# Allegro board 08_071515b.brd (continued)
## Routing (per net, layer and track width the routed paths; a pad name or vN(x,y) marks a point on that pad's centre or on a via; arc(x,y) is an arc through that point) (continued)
ID0: length 18
  TOP w0.14: v2(52.2,10.54) 53.09,10.54 R136.2 53.22,9.6 52.83,9.2 U26.1
  L8_SIG w0.127: v2(52.2,10.54) 50.29,8.64 40.23,8.64 v1(39.42,7.83)
  BOTTOM w0.14: J2.76 v1(39.42,7.83)
ID1: length 17
  TOP w0.14: R137.2 v2(52.45,5.84) 52.45,7.19 U26.3
  L8_SIG w0.127: v2(52.45,5.84) 49.99,8.31 40.53,8.31 v1(40.05,7.83)
  BOTTOM w0.14: J2.78 v1(40.05,7.83)
INTVCC: length 16.7
  TOP w0.254: v2(24.83,13.08) 23.24,13.08 22.55,13.77 R100.2 20.43,14.62 20.42,14.62 20.23,14.81 20.23,14.81 20.05,14.99 VR1.3
  TOP w0.305: R94.2 v2(15.34,12.17)
  L8_SIG w0.305: v2(24.83,13.08) 21.4,13.08 21.14,12.83 16,12.83 v2(15.34,12.17)
JTG0_TCK/SWCLK: length 70.6
  TOP w0.14: v1(5.46,28.83) 4.27,28.83 2.71,30.39 2.71,46.84 1.94,47.6 1.94,55.25 3.04,56.34 5.51,56.34 6.03,55.82 6.03,54.67 5.08,53.72
  TOP w0.203: U1.B11 v1(33.82,59.74)
  L5_SIG w0.127: v1(33.82,59.74) 33.07,58.99 33.07,57.25 32.75,56.93 20.1,56.93 16.13,52.96 6.68,52.96 5.92,53.72 5.08,53.72
  BOTTOM w0.14: v1(5.46,28.83) 5.59,28.7 J3.50
JTG0_TD0/SW0: length 77.7
  TOP w0.14: v1(8.26,27.81) 4.65,27.81 2.35,30.12 2.35,46.64 1.46,47.52 1.46,56.2 2.16,56.9 5.71,56.9 6.48,56.13 6.48,53.85 P6.6
  TOP w0.203: U1.C11 v1(33.82,58.94)
  L5_SIG w0.127: v1(33.82,58.94) 33.38,58.5 33.38,56.87 32.64,56.13 19.94,56.13 16.26,52.45 P6.6
  BOTTOM w0.14: J3.52 8,28.07 v1(8.26,27.81)
JTG0_TDI: length 85.4
  TOP w0.14: 5.08,51.18 6.92,53.02 6.92,56.39 5.84,57.47 1.46,57.47 0.86,56.86 0.86,47.47 2.01,46.32 2.01,29.84 4.8,27.05 v1(8.26,27.05)
  TOP w0.203: U1.C13 v1(35.42,59.74)
  L5_SIG w0.127: 5.08,51.18 5.84,51.18 6.73,52.07 16.38,52.07 20.07,55.75 23.75,55.75 24.15,55.35 32.87,55.35 34.21,56.68 34.21,59.07 34.46,59.33 35.01,59.33 v1(35.42,59.74)
  BOTTOM w0.14: J3.54 7.87,27.43 v1(8.26,27.05)
JTG0_TMS/SWDIO: length 72
  TOP w0.14: v1(8.26,29.08) 7.91,29.43 4.29,29.43 3.1,30.62 3.1,47 2.28,47.82 2.28,55.11 3.17,56.01 4.83,56.01 5.08,55.75 P6.2
  TOP w0.203: U1.C12 v1(34.62,59.74)
  L5_SIG w0.127: P6.2 5.92,54.99 7.57,53.34 16,53.34 17.14,54.48 17.14,56.01 18.41,57.28 24,57.28 24.45,57.73 32.63,57.73 32.79,57.89 32.79,59.59 33.4,60.2 34.16,60.2 v1(34.62,59.74)
  BOTTOM w0.14: v1(8.26,29.08) 8,29.34 J3.48
JTG0_TRST*: length 75.3
  TOP w0.14: P6.9 6.1,47.62 R78.2 R79.1 v1(9.02,45.54) ; v1(19.68,64.14) 29.42,64.14 U1.A10
  L4_SIG w0.127: v1(5.46,26.54) 6.48,27.56 6.48,42.99 v1(9.02,45.54)
  L5_SIG w0.127: P6.9 2.92,49.91 2.41,50.42 2.41,55.37 3.56,56.52 11.18,56.52 12.07,55.63 12.83,55.63 13.44,56.24 15.6,56.24 18.67,59.31 19.43,59.31 19.68,59.56 v1(19.68,64.14)
  BOTTOM w0.14: v1(5.46,26.54) 5.72,26.8 J3.56
LTC3310_EN: length 2.3
  TOP w0.254: U16.1 33.66,15.64 33.66,14.99 33.91,14.73 v2(33.91,14.54)
  BOTTOM w0.254: v2(33.91,14.54) 33.91,13.6 R92.2
PA_00/SPI2_MISO/XSPI0_MISO/PWM0_AH/SMC0_D00: length 38.7
  TOP w0.14: U23.6 21.99,30.88 21.46,30.35 v1(21.46,30.1) ; v1(22.35,35.43) 22.35,36.16 U22.6
  TOP w0.203: U1.N3 v1(26.62,50.94)
  L7_SIG w0.127: v1(22.35,35.43) 21.97,35.81 19.81,35.81 18.57,37.06 18.57,44.6 19.68,45.72 20.7,45.72 22.1,47.12 22.1,51.56 22.69,52.15 26.78,52.15 27.03,51.9 27.03,51.35 v1(26.62,50.94)
  L8_SIG w0.127: v1(22.35,35.43) 22.35,33.93 21.64,33.22 20.14,33.22 19.91,32.99 19.91,30.45 20.27,30.1 v1(21.46,30.1)
PA_00/SPI2_MISO/XSPI0_MISO/PWM0_AH/SMC0_D00_Z: length 33.6
  TOP w0.14: v1(21.46,30.99) 21.85,31.38 U23.5
  L5_SIG w0.127: v1(21.46,30.99) 22.07,30.38 22.07,9.07 22.76,8.38 22.76,7.7 22.19,7.14 19.47,7.14 v1(16.56,4.23)
  BOTTOM w0.14: J2.3 v1(16.56,4.23)
PA_01/SPI2_MOSI/XSPI0_MOSI/PWM0_AL/SMC0_D01: length 30.3
  TOP w0.14: v1(21.46,32.77) 21.85,32.38 U23.3 ; U22.3 21.85,37.71 v1(21.46,38.1)
  TOP w0.203: U1.P3 v1(26.62,50.14)
  L4_SIG w0.127: v1(21.46,38.1) 21.92,37.64 21.92,33.22 v1(21.46,32.77)
  L7_SIG w0.127: v1(26.62,50.14) 26.57,50.14 26.23,50.47 26.23,51.24 26.14,51.33 22.62,51.33 22.48,51.18 22.48,46.86 18.9,43.28 18.9,38.51 19.3,38.1 v1(21.46,38.1)
PA_01/SPI2_MOSI/XSPI0_MOSI/PWM0_AL/SMC0_D01_Z: length 38.9
  TOP w0.14: U23.2 21.99,32.88 21.46,33.4 v1(21.46,33.66)
  L5_SIG w0.127: v1(17.19,1.94) 17.19,4.31 19.68,6.81 22.45,6.81 23.09,7.44 23.09,8.52 22.48,9.13 22.48,32.64 v1(21.46,33.66)
  BOTTOM w0.14: J2.5 v1(17.19,1.94)
PA_02/SPI2_D2/XSPI0_D2/TWI3_SCL/SMC0_D02/TM0_ACLK3: length 27.3
  TOP w0.14: U22.8 v1(25.32,35.51) ; U23.8 v1(25.32,30.18)
  TOP w0.203: U1.P2 v1(25.82,50.14)
  L7_SIG w0.127: v1(25.82,50.14) 25.41,50.55 24.13,50.55 23.47,49.89 23.47,45.45 21.77,43.75 21.77,39.87 23.23,38.4 24.76,38.4 25.32,37.84 v1(25.32,35.51) v1(25.32,30.18)
PA_02/SPI2_D2/XSPI0_D2/TWI3_SCL/SMC0_D02/TM0_ACLK3_Z: length 35
  TOP w0.14: U23.9 26.02,30.88 26.54,30.35 v1(26.54,30.1)
  L5_SIG w0.127: v1(17.83,4.23) 20.03,6.43 22.91,6.43 23.97,7.49 23.97,11.73 23.09,12.62 23.09,16.69 24.84,18.44 25.69,18.44 26.29,19.04 26.29,27.69 26.06,27.91 26.06,29.62 v1(26.54,30.1)
  BOTTOM w0.14: J2.7 v1(17.83,4.23)
PA_03/SPI2_D3/XSPI0_D3/TWI3_SDA/SMC0_D03: length 26.8
  TOP w0.14: v1(26.54,38.1) 26.15,37.71 U22.12 ; v1(26.54,32.77) 26.15,32.38 U23.12
  TOP w0.203: U1.R3 v1(26.62,49.34)
  L4_SIG w0.127: v1(26.54,32.77) 26.09,33.22 26.09,37.64 v1(26.54,38.1)
  L7_SIG w0.127: v1(26.62,49.34) 26.21,49.75 24.23,49.75 23.75,49.28 23.75,45.34 22.1,43.69 22.1,40.01 23.37,38.73 24.89,38.73 25.65,37.97 25.93,37.97 26.06,38.1 v1(26.54,38.1)
PA_03/SPI2_D3/XSPI0_D3/TWI3_SDA/SMC0_D03_Z: length 38.3
  TOP w0.14: U23.11 v1(26.54,31.88)
  L5_SIG w0.127: v1(26.54,31.88) 27,31.42 27,27.76 26.67,27.43 26.67,18.95 25.83,18.11 24.97,18.11 23.42,16.55 23.42,12.76 24.38,11.79 24.38,7.12 23.31,6.05 21.05,6.05 18.46,3.46 v1(18.46,1.94)
  BOTTOM w0.14: J2.9 v1(18.46,1.94)
PA_04/SPI2_CLK/XSPI0_CLK/PWM0_BH/SMC0_D04: length 24
  TOP w0.14: v1(27.81,32.77) 28.2,32.38 U28.3 ; v1(27.81,38.1) 28.2,37.71 U27.3
  TOP w0.203: U1.R1 v1(25.02,49.34)
  L4_SIG w0.127: v1(27.81,38.1) 27.38,37.67 27.38,33.15 27.76,32.77 v1(27.81,32.77)
  L7_SIG w0.127: v1(25.02,49.34) 24.54,49.34 24.03,48.83 24.03,45.22 23.29,44.49 23.29,40.5 23.79,40.01 23.79,39.46 24.18,39.07 25.03,39.07 25.56,38.53 27.38,38.53 v1(27.81,38.1)
PA_04/SPI2_CLK/XSPI0_CLK/PWM0_BH/SMC0_D04_Z: length 41.2
  TOP w0.14: U28.2 28.34,32.88 27.81,33.4 v1(27.81,33.66)
  L5_SIG w0.127: v1(19.1,1.94) 19.1,3.63 20.58,5.11 23.4,5.11 23.55,5.26 23.55,5.66 25.24,7.35 25.24,11.4 23.75,12.89 23.75,16.42 25.11,17.78 25.96,17.78 27,18.82 27,27.2 27.38,27.58 27.38,33.22 v1(27.81,33.66)
  BOTTOM w0.14: J2.11 v1(19.1,1.94)
PA_05/SPI2_SEL1B/XSPI0_SEL1B/FPLL_DBG_LOCK/SMC0_D05/SPI2_SSB: length 28.3
  TOP w0.14: U27.6 28.34,36.21 27.81,35.69 v1(27.81,35.43) ; v1(27.81,30.1) 27.81,30.35 28.34,30.88 U28.6
  TOP w0.203: U1.T2 v1(25.82,48.54)
  L4_SIG w0.127: v1(27.81,35.43) 28.24,35 28.24,30.53 v1(27.81,30.1)
  L7_SIG w0.127: v1(25.82,48.54) 25.43,48.93 24.67,48.93 24.31,48.56 24.31,44.75 23.62,44.07 23.62,40.64 24.06,40.21 24.94,40.21 25.53,39.62 27.81,39.62 28.57,38.86 28.57,36.2 v1(27.81,35.43)
PA_05/SPI2_SEL1B/XSPI0_SEL1B/FPLL_DBG_LOCK/SMC0_D05/SPI2_SSB_Z: length 38.6
  TOP w0.14: U28.5 28.2,31.38 v1(27.81,30.99)
  L5_SIG w0.127: v1(27.81,30.99) 28.24,30.56 28.24,27.76 27.36,26.87 27.36,18.7 26.1,17.45 25.25,17.45 24.08,16.28 24.08,13.03 25.59,11.52 25.59,7.05 24.64,6.1 24.64,5.26 24.18,4.8 20.8,4.8 19.73,3.73 v1(19.73,1.94)
  BOTTOM w0.14: J2.13 v1(19.73,1.94)
PA_06/SPI0_CLK/UART0_TXB/XSPI0_D4/SMC0_D06/TM0_ACLK1: length 61.4
  TOP w0.14: U29.3 34.55,37.71 v1(34.16,38.1) ; U7.9 18.32,75.82 v2(20.19,75.82) ; v1(34.16,32.77) 34.55,32.38 U30.3
  TOP w0.203: U1.T3 v1(27.42,48.54)
  L4_SIG w0.127: v2(20.19,75.82) 20.19,75.82 19.43,75.06 19.43,74.42 19.94,73.91 21.21,73.91 21.97,73.15 21.97,49.02 22.35,48.64 24.26,48.64 24.54,48.93 27.03,48.93 v1(27.42,48.54) ; v1(34.16,38.1) 33.71,37.64 33.71,33.22 v1(34.16,32.77)
  L7_SIG w0.127: v1(34.16,38.1) 33.73,38.53 33.73,40.08 34.29,40.64 34.29,41.53 33.02,42.8 28.57,42.8 27.71,43.67 27.71,44.79 27.81,44.89 27.81,48.13 27.42,48.53 v1(27.42,48.54)
PA_06/SPI0_CLK/UART0_TXB/XSPI0_D4/SMC0_D06/TM0_ACLK1_Z: length 62.2
  TOP w0.14: v1(16.56,5.54) 17.27,4.83 17.27,3.68 18.29,2.67 28.53,2.67 v1(29.26,1.94) ; U30.2 34.69,32.88 34.16,33.4 v1(34.16,33.66)
  L5_SIG w0.127: v1(34.16,33.66) 33.66,33.15 33.66,31.75 33.35,31.45 31.95,31.45 29.44,28.93 29.44,27.76 28.55,26.87 28.55,8.67 28.07,8.19 28.07,6.73 28.57,6.22 28.57,5.4 28.26,5.08 27.33,5.08 26.8,4.55 26.8,3.05 27.9,1.94 v1(29.26,1.94)
  BOTTOM w0.14: J2.15 20.37,3.99 20.23,4.13 18.7,4.13 18.13,4.7 17.4,4.7 v1(16.56,5.54) J2.4 ; J2.43 v1(29.26,1.94)
PA_07/SPI0_MISO/UART0_RXB/XSPI0_D5/SMC0_D07/TM0_ACI0: length 72.7
  TOP w0.14: U29.6 34.69,36.21 34.16,35.69 v1(34.16,35.43) ; U30.6 34.69,30.88 34.16,30.35 v1(34.16,30.1) ; U7.12 v2(16.19,77.74)
  TOP w0.203: U1.V1 v1(25.02,46.94)
  L4_SIG w0.127: v1(34.16,35.43) 34.59,35 34.59,30.53 v1(34.16,30.1) ; v2(16.19,77.74) 17.26,77.74 17.53,77.47 17.53,75.44 16.76,74.68 16.76,73.53 17.14,73.15 17.14,70.99 18.41,69.72 18.41,67.95 18.8,67.56 18.8,65.53 18.67,65.41 17.78,65.41 17.57,65.19 17.57,60.28 17.91,59.94 17.91,57.28 16.81,56.18 16.81,51.89 18.8,49.91 18.8,47.5 19.35,46.94 v1(25.02,46.94)
  L7_SIG w0.127: v1(34.16,35.43) 33.71,35.89 32.26,35.89 32.13,36.02 32.13,40.01 32.65,40.53 32.65,41.12 32.11,41.66 26.16,41.66 25.21,42.61 25.21,43.69 25.41,43.88 25.41,46.6 25.07,46.94 v1(25.02,46.94)
PA_07/SPI0_MISO/UART0_RXB/XSPI0_D5/SMC0_D07/TM0_ACI0_Z: length 58.6
  TOP w0.14: v1(34.16,30.99) 34.55,31.38 U30.5 ; v1(21,1.94) 21.77,1.17 31.78,1.17 32.38,1.78 32.38,4.32 31.95,4.76 30.17,4.76 v1(29.72,4.3)
  L5_SIG w0.127: v1(29.72,4.3) 29.72,4.79 29.89,4.96 29.89,6.05 29.05,6.89 29.05,14.68 29.82,15.44 29.82,17.75 28.96,18.62 28.96,26.59 29.77,27.41 29.77,28.57 30.95,29.75 31.93,29.75 32.18,30 32.74,30.56 33.73,30.56 v1(34.16,30.99)
  BOTTOM w0.14: J2.6 17.19,5.61 17.72,5.08 18.16,5.08 18.8,4.45 20.72,4.45 21,4.16 J2.17 v1(21,1.94) ; v1(29.72,4.3) 29.72,4.19 29.89,4.02 J2.45
PA_08/SPI0_MOSI/UART0_RTSB/XSPI0_D6/SMC0_D08/TM0_ACLK2: length 73.5
  TOP w0.14: v2(11.05,78.74) 11.4,78.39 U7.2 ; U30.8 v1(38.1,30.18) ; U29.8 v1(38.1,35.51)
  TOP w0.203: U1.U3 v1(26.62,47.74)
  L4_SIG w0.127: v2(19.3,73.41) 20.95,73.41 21.43,72.93 21.43,48.67 21.97,48.13 26.16,48.13 26.55,47.74 v1(26.62,47.74) ; v1(38.1,30.18) v1(38.1,35.51)
  L5_SIG w0.127: v2(19.3,73.41) 19.3,74.17 18.29,75.18 16,75.18 12.45,78.74 v2(11.05,78.74)
  L7_SIG w0.127: v1(26.62,47.74) 26.62,47.67 27.01,47.29 27.01,44.85 26.92,44.77 26.92,42.93 27.43,42.42 32.51,42.42 33.39,41.54 33.39,37.99 33.71,37.67 34.72,37.67 35.43,36.96 35.43,36.32 36.24,35.51 v1(38.1,35.51)
PA_08/SPI0_MOSI/UART0_RTSB/XSPI0_D6/SMC0_D08/TM0_ACLK2_Z: length 54.4
  TOP w0.14: U30.9 38.72,30.88 39.24,30.35 v1(39.24,30.1) ; v1(30.53,4.23) 29.35,3.05 22.82,3.05 v1(21.64,4.23)
  L5_SIG w0.127: v1(30.53,4.23) 31.25,3.51 36.5,3.51 38.07,5.08 38.07,18.48 36.25,20.31 36.25,27.1 v1(39.24,30.1)
  BOTTOM w0.14: J2.8 17.83,5.61 17.98,5.46 18.27,5.46 18.97,4.76 21.1,4.76 v1(21.64,4.23) J2.19 ; J2.47 v1(30.53,4.23)
PA_09/SPI0_SEL1B/UART0_CTSB/XSPI0_D7/SMC0_D09/SPI0_SSB: length 76.7
  TOP w0.14: v1(39.24,32.77) 38.85,32.38 U30.12 ; v1(39.24,38.1) 38.85,37.71 U29.12 ; U7.5 v2(13.86,76.44)
  TOP w0.203: U1.V2 v1(25.82,46.94)
  L4_SIG w0.127: v2(18.16,64.77) 19.3,63.63 19.3,47.62 19.58,47.35 25.41,47.35 v1(25.82,46.94) ; v1(39.24,32.77) 38.81,33.2 38.81,37.67 v1(39.24,38.1)
  L5_SIG w0.127: v2(13.86,76.44) 15.49,74.8 18.03,74.8 18.41,74.42 18.41,73.66 17.53,72.77 17.53,71.63 18.69,70.46 18.69,65.3 v2(18.16,64.77)
  L7_SIG w0.127: v1(39.24,38.1) 38.73,37.59 38.73,35.18 38.61,35.05 36.2,35.05 34.49,36.75 32.71,36.75 32.46,37.01 32.46,39.83 33.02,40.39 33.02,41.22 32.2,42.04 26.92,42.04 26.42,42.55 26.42,43.69 26.21,43.9 26.21,46.44 25.82,46.82 v1(25.82,46.94)
PA_09/SPI0_SEL1B/UART0_CTSB/XSPI0_D7/SMC0_D09/SPI0_SSB_Z: length 57
  TOP w0.14: v1(22.27,1.94) 22.71,1.5 30.33,1.5 31.02,2.19 31.02,3.97 v1(31.37,4.32) ; U30.11 v1(39.24,31.88)
  L5_SIG w0.127: v1(39.24,31.88) 38.58,31.22 38.58,29.95 35.86,27.23 35.86,20.22 37.74,18.34 37.74,5.74 35.84,3.84 31.85,3.84 v1(31.37,4.32)
  BOTTOM w0.14: v1(22.27,1.94) J2.21 22.27,4.27 21.49,5.05 19.2,5.05 18.46,5.79 J2.10 ; J2.49 31.16,4.11 v1(31.37,4.32)
PA_10/TWI0_SCL/SPI1_CLK/TM0_TMR0/SMC0_D10: length 80.5
  TOP w0.14: R49.1 v2(20.57,32.64)
  TOP w0.203: U1.U2 v1(25.82,47.74)
  L4_SIG w0.127: v2(20.57,32.64) 19.43,31.5 19.43,29.51 18.21,28.3 15.88,28.3 15.27,27.69 15.27,24.33 16.7,22.9 16.7,11.62 15.19,10.11 15.19,8.66 16.02,7.83 v1(19.73,7.83)
  L7_SIG w0.127: v2(20.57,32.64) 18.24,34.98 18.24,45.54 19.81,47.12 21.08,47.12 21.72,47.75 21.72,52.96 22.08,53.33 27.32,53.33 27.83,52.81 27.83,49.75 v1(25.82,47.74)
  BOTTOM w0.14: J2.31 25.45,4.27 25.02,4.7 22.35,4.7 21.71,5.35 20,5.35 19.73,5.61 J2.14 v1(19.73,7.83)
PA_11/TWI0_SDA/SPI1_MISO/HADC_EOC_OUT/SMC0_D11/TM0_ACI4: length 89.6
  TOP w0.14: R52.2 v2(20.57,35.18)
  TOP w0.203: U1.V8 v1(30.62,46.94)
  L4_SIG w0.127: v1(20.37,7.83) 20.37,7.35 20.21,7.19 16.05,7.19 14.76,8.48 14.76,10.19 16.37,11.8 16.37,22.76 14.94,24.2 14.94,27.86 15.7,28.63 18.07,28.63 19.08,29.63 19.08,33.68 v2(20.57,35.18)
  L8_SIG w0.127: v2(20.57,35.18) 20.07,35.69 12.7,35.69 9.53,38.86 9.53,44.07 11.43,45.97 20.44,45.97 20.46,45.95 21.82,45.95 23.2,47.33 30.23,47.33 v1(30.62,46.94)
  BOTTOM w0.14: v1(20.37,7.83) J2.16 20.37,5.78 20.51,5.64 21.92,5.64 22.48,5.08 25.16,5.08 26.08,4.16 J2.33
PA_12/FLG0/SPI1_MOSI/TM0_TMR1/SMC0_D12: length 86.1
  TOP w0.14: U4.D3 14.22,35.42 14.22,37.21 15.62,38.61 v2(17.53,38.61)
  TOP w0.203: U1.W6 v1(29.02,46.14)
  L4_SIG w0.127: v1(21,7.83) 21.79,7.04 24.01,7.04 24.33,7.36 24.33,8.01 24.71,8.39 24.71,11.44 22.71,13.45 22.71,28.59 25.4,31.28 25.4,34.67 24.89,35.18 24.89,35.82 25.52,36.44 25.52,39.8 27.62,41.91 28.31,41.91 29.59,43.19 29.59,44.07 29.43,44.23 29.43,45.73 v1(29.02,46.14)
  L8_SIG w0.127: v2(17.53,38.61) 12.57,38.61 11.94,39.24 11.94,40.26 10.54,41.66 10.54,43.94 11.84,45.24 18.52,45.24 18.54,45.21 23.62,45.21 24.14,45.73 28.61,45.73 v1(29.02,46.14)
  BOTTOM w0.14: J2.18 v1(21,7.83)
PA_13/FLG1/SPI1_SEL1B/TM0_TMR2/SMC0_D13/SPI1_SSB: length 63.8
  TOP w0.14: U9.2 v2(16.32,41.27)
  TOP w0.203: U1.Y6 v1(29.02,45.34)
  L4_SIG w0.127: v1(21.64,7.83) 22.1,7.37 23.88,7.37 24,7.49 24,8.38 24.38,8.76 24.38,11.3 22.38,13.31 22.38,28.73 24.21,30.56 24.21,38.3 25.18,39.28 25.18,41.82 25.78,42.42 27.43,42.42 29.02,44.01 v1(29.02,45.34)
  L8_SIG w0.127: v1(29.02,45.34) 28.51,44.83 28.51,44.57 28.68,44.4 28.68,43.99 28.51,43.82 28.51,42.8 28,42.29 19.43,42.29 18.41,41.27 v2(16.32,41.27)
  BOTTOM w0.14: J2.20 v1(21.64,7.83)
PA_14/TWI2_SCL/SPI1_D2/UART1_RXB/SMC0_D14/TM0_ACI1: length 107.8
  TOP w0.14: v2(52.83,21.21) 52.83,23.11 52.71,23.24 U21.2 ; U10.2 v2(10.09,41.27)
  TOP w0.203: U1.W7 v1(29.82,46.14)
  L4_SIG w0.127: v1(25.45,5.54) 25.45,9.91 27.46,11.92 27.46,14.2 26.87,14.78 26.41,14.78 26.06,15.13 26.06,15.4 26.06,17.93 27.3,19.18 27.3,28.45 v1(26.54,29.21) 27,29.67 28.73,29.67 29.18,30.12 29.18,34.21 29.17,34.23 29.17,40.17 29.57,40.56 29.57,41.88 30.1,42.42 30.1,44.07 30.23,44.2 30.23,45.73 v1(29.82,46.14)
  L8_SIG w0.127: v1(29.82,46.14) 29.41,46.55 24.33,46.55 23.37,45.59 11.72,45.59 10.09,43.96 v2(10.09,41.27) ; v1(26.54,29.21) 27.18,28.57 28.19,28.57 28.5,28.88 41.99,28.88 46.23,24.64 46.23,20.96 46.57,20.61 52.23,20.61 v2(52.83,21.21)
  BOTTOM w0.14: J2.32 v1(25.45,5.54)
PA_15/TWI2_SDA/SPI1_D3/UART1_TXB/SMC0_D15/FPLL_REF_CLK: length 97.6
  TOP w0.14: v2(12.26,41.27) U5.2 ; U20.2 48.2,23.24 48.39,23.05 v2(48.39,21.21)
  TOP w0.203: U1.W8 v1(30.62,46.14)
  L4_SIG w0.127: v1(26.08,7.83) 26.08,9.95 27.79,11.66 27.79,14.38 27.05,15.11 26.54,15.11 26.39,15.27 26.39,17.63 27.81,19.05 v1(27.81,29.21) 29.18,29.21 30.15,30.18 30.15,41.68 31.11,42.65 31.11,44.2 31.01,44.3 31.01,45.75 v1(30.62,46.14)
  L8_SIG w0.127: v2(48.39,21.21) 48.12,20.94 46.88,20.94 46.61,21.21 46.61,24.76 43.21,28.16 43.21,28.16 42.89,28.47 42.89,28.48 42.16,29.21 v1(27.81,29.21) ; v2(12.26,41.27) 13.27,40.26 18.29,40.26 19.94,41.91 29.08,41.91 29.45,42.28 29.45,44.4 29.43,44.42 29.43,45.5 29.66,45.73 30.21,45.73 v1(30.62,46.14)
  BOTTOM w0.14: J2.34 v1(26.08,7.83)
PB_00/MLB0_DAT/TWI1_SCL/UART1_RTSB/SMC0_AMS0B/TM0_ACI3: length 92.6
  TOP w0.14: R30.1 v2(12.7,69.98) ; U3.2 v2(41.53,26.92)
  TOP w0.203: U1.A7 v1(29.82,61.34)
  L5_SIG w0.127: v1(50.16,60.83) 49.1,61.9 41.07,61.9 40.93,61.75 39.21,61.75 38.99,61.98 30.46,61.98 v1(29.82,61.34)
  L7_SIG w0.127: v1(50.16,60.83) 49.4,60.07 49.4,58.47 50.95,56.92 52.3,56.92 52.58,56.64 52.58,43.69 51.68,42.79 51.68,28.95 51.31,28.57 48.01,28.57 46.35,26.92 v2(41.53,26.92) ; v2(12.7,69.98) 22.35,69.98 29.82,62.51 v1(29.82,61.34)
PB_00/MLB0_DAT/TWI1_SCL/UART1_RTSB/SMC0_AMS0B/TM0_ACI3_Z: length 83.2
  TOP w0.14: U3.4 v2(46.34,25.97)
  L5_SIG w0.127: v1(49.78,4.45) 49.78,6.46 46.34,9.91 v2(46.34,25.97) 47.3,25.97 47.88,25.4 48.77,25.4 50.04,26.67 50.04,27.81 50.42,28.19 51.18,28.19 51.69,28.7 51.69,42.04 53.98,44.32 56.01,44.32 56.77,43.56 v1(58.04,43.56)
  L8_SIG w0.127: v1(49.78,4.45) 48.59,3.25 27.36,3.25 26.72,3.89 v1(26.72,5.54)
  BOTTOM w0.14: J1.100 57.66,43.94 v1(58.04,43.56) ; J2.35 v1(26.72,5.54) J2.36
PB_01/MLB0_SIG/TWI1_SDA/UART1_CTSB/SMC0_AREB/TM0_CLK: length 127.4
  TOP w0.14: U19.2 v2(48.51,26.92) ; R29.1 v2(13.97,71.88)
  TOP w0.203: U1.C9 v1(31.42,59.74)
  L7_SIG w0.127: v1(31.42,59.74) 31.83,60.15 32.47,60.15 32.64,60.33 32.64,61.34 22.1,71.88 v2(13.97,71.88)
  L8_SIG w0.127: v1(31.42,59.74) 30.23,58.55 24.07,58.55 23.75,58.23 18.3,58.23 16.89,56.82 16.89,54.23 14.1,51.44 10.79,51.44 7.82,48.46 7.82,43.89 4.19,40.26 4.19,32.13 4.95,31.37 10.92,31.37 11.43,31.88 14.48,31.88 17.81,28.55 24.99,28.55 26.09,29.64 42.37,29.64 42.78,29.23 43.65,29.23 43.96,28.92 43.96,28.05 45.09,26.92 v2(48.51,26.92)
PB_01/MLB0_SIG/TWI1_SDA/UART1_CTSB/SMC0_AREB/TM0_CLK_Z: length 84.9
  TOP w0.14: U19.4 51.12,25.97 v2(51.44,26.29)
  L5_SIG w0.127: v1(54.86,43.81) 53.97,43.81 52.07,41.91 52.07,27.69 51.44,27.05 v2(51.44,26.29) 51.85,25.88 52.74,25.88 53.21,25.4 53.21,24.7 52.39,23.88 47.82,23.88 46.74,22.8 46.74,16.46 49.91,13.29 49.91,7.37 51.13,6.15 51.13,4.14 51,4.01 48.95,4.01 46.74,6.22 40.39,6.22 40.01,5.84 40.01,5.33 37.85,3.17 30.14,3.17 29.29,4.03 29.29,4.5 29.09,4.69 27.81,4.69 v1(27.35,4.23)
  BOTTOM w0.14: J1.98 55.37,43.31 v1(54.86,43.81) ; J2.38 v1(27.35,4.23) J2.37
PB_02/MLB0_CLK/FLG3/LP1_ACK/SMC0_AWEB/TM0_ACLK4: length 92.1
  TOP w0.203: U1.B8 v1(30.62,60.54)
  L5_SIG w0.127: v1(50.16,59.94) 49.53,60.58 42.55,60.58 42.17,60.95 31.03,60.95 v1(30.62,60.54)
  L7_SIG w0.127: v1(50.16,59.94) 49.73,59.51 49.73,58.72 50.04,58.42 51.82,58.42 53.09,57.15 53.09,48.51 55.3,46.3 55.3,42.98 54.61,42.29 v1(53.85,42.29) 52.96,42.29 52.01,41.35 52.01,27.73 53.21,26.53 53.21,24.38 50.98,22.15 50.98,17.24 52.73,15.48 52.73,8.92 48.76,4.95 46.99,4.95 v1(46.4,5.54)
  BOTTOM w0.14: v1(53.85,42.29) 54.23,42.67 J1.96 ; J2.98 v1(46.4,5.54)
PB_03/TM0_TMR3/FLG2/SPI2_SEL2B/SMC0_ADDR1/CNT0_UD: length 163.7
  TOP w0.14: v1(31.16,5.54) 30.05,5.54 29.55,5.03 27.6,5.03 27.3,5.33 27.3,5.84 26.92,6.22 24,6.22 23.37,5.59 23.37,4.69 v1(22.91,4.23)
  TOP w0.203: U1.C7 v1(29.82,59.74)
  L5_SIG w0.127: v1(51.18,62.36) 50.16,62.36 49.15,63.37 48,63.37 47.19,62.55 41.33,62.55 40.89,62.99 39.24,62.99 38.86,62.61 28.96,62.61 28.63,62.29 28.63,60.27 28.77,60.13 29.43,60.13 v1(29.82,59.74)
  L7_SIG w0.127: v1(54.86,40.26) 55.35,40.26 55.5,40.26 56.52,41.28 56.52,46.61 54.36,48.77 54.36,59.18 v1(51.18,62.36)
  L8_SIG w0.127: v1(31.16,5.54) 30.35,6.35 17.14,6.35 16.26,7.24 11.81,7.24 6.4,12.65 6.4,17.95 3.48,20.87 3.48,40.11 3.48,40.39 3.53,40.44 3.53,40.53 7.09,44.09 7.09,48.66 10.52,52.1 13.78,52.1 16.23,54.54 16.23,57.1 19.59,60.45 23.69,60.45 24,60.13 24,60.13 29.41,60.13 29.8,59.74 v1(29.82,59.74)
  BOTTOM w0.14: J2.50 v1(31.16,5.54) ; v1(54.86,40.26) 55.35,40.26 55.48,40.13 J1.88 ; J2.23 v1(22.91,4.23)
PB_04/TM0_TMR4/SPI1_RDY/LP0_ACK/SMC0_ADDR2/CNT0_ZM: length 125.2
  TOP w0.14: v1(24.18,5.54) 24.98,4.74 29.74,4.74 30.08,5.08 38.99,5.08 39.75,4.32 39.75,2.67 41.28,1.14 45.6,1.14 v1(46.4,1.94)
  TOP w0.203: U1.B7 v1(29.82,60.54)
  L5_SIG w0.127: v1(50.16,61.72) 49.66,62.23 41.15,62.23 40.77,62.61 39.26,62.61 38.98,62.33 30.07,62.33 29.43,61.69 29.43,60.93 v1(29.82,60.54)
  L7_SIG w0.127: v1(46.4,1.94) 53.06,8.6 53.06,15.62 51.31,17.37 51.31,22.01 53.54,24.25 53.54,26.67 52.34,27.87 52.34,40.41 53.21,41.27 v1(53.85,41.27) 54.36,40.77 55.25,40.77 56.13,41.66 56.13,46.52 53.98,48.68 53.98,58.42 50.67,61.72 v1(50.16,61.72)
  BOTTOM w0.14: J2.97 v1(46.4,1.94) ; J1.90 55.75,40.77 54.36,40.77 v1(53.85,41.27) ; J2.28 v1(24.18,5.54)
PB_05/TM0_TMR5/SPI2_RDY/SPI0_SEL2B/SMC0_ADDR3/CNT0_DG: length 150.4
  TOP w0.203: U1.C8 v1(30.62,59.74)
  L5_SIG w0.127: v1(30.62,59.74) 31.01,60.13 32.44,60.13 32.89,60.58 34.54,60.58 34.97,60.15 41.18,60.15 41.22,60.2 49.02,60.2 v1(50.16,59.05)
  L7_SIG w0.127: v1(54.86,41.27) 55.64,42.05 55.64,46.55 53.59,48.6 53.59,57.4 51.94,59.05 v1(50.16,59.05)
  L8_SIG w0.127: v1(31.8,7.83) 31.23,7.26 25.38,7.26 v1(24.81,7.83) 23.72,6.73 17.4,6.73 16.51,7.62 11.94,7.62 6.73,12.83 6.73,18.09 3.81,21.01 3.81,40.25 3.86,40.3 3.86,40.4 7.49,44.03 7.49,48.6 10.66,51.77 13.92,51.77 16.56,54.41 16.56,56.96 18.96,59.35 30.23,59.35 v1(30.62,59.74)
  BOTTOM w0.14: J1.92 55.48,41.4 55.35,41.27 v1(54.86,41.27) ; J2.12 19.1,8.05 19.43,8.38 24.26,8.38 v1(24.81,7.83) J2.30 ; J2.52 v1(31.8,7.83)
PB_06/LP0_CLK/SPI1_SEL5B/PWM0_BL/TRACE0_CLK: length 64.8
  TOP w0.203: U1.V5 v1(28.22,46.94)
  L4_SIG w0.127: v1(28.22,46.94) 28.63,46.53 32.47,46.53 32.77,46.23 32.77,42.8 33.27,42.29 33.53,42.29 35.46,40.36 35.46,19.53 37.97,17.02 37.97,14.22 37.34,13.59 37.34,10.67 36.68,10.01 36.68,6.5 38.99,4.19 38.99,2.16 40.01,1.14 43.05,1.14 43.31,1.4 43.31,2.41 44.32,3.43 46.24,3.43 v1(47.04,4.23)
  BOTTOM w0.14: J2.99 v1(47.04,4.23)
PB_07/LP0_D0/SPI2_SEL5B/TRACE0_D00: length 90.4
  TOP w0.203: U1.W4 v1(27.42,46.14)
  L4_SIG w0.127: v1(27.42,46.14) 27.03,46.53 24.17,46.53 23.49,45.85 20.57,45.85 19.81,45.09 19.81,44.22 18.49,42.9 18.49,34.41 18.41,34.33 18.41,29.9 17.8,29.29 15.42,29.29 14.27,28.14 14.27,24.54 14.27,24.26 14.27,24.26 14.27,14.27 13.08,13.08 v1(13.08,4.83)
  L5_SIG w0.127: v1(13.08,4.83) 13.7,4.83 17.08,1.45 44.09,1.45 44.48,1.83 44.48,2.94 v1(45.77,4.23)
  BOTTOM w0.14: J2.95 v1(45.77,4.23)
PB_08/LP0_D1/SPI1_SEL7B/TM0_TMR6/TRACE0_D01: length 86.7
  TOP w0.203: U1.W3 v1(26.62,46.14)
  L4_SIG w0.127: v1(26.62,46.14) 26.21,45.73 24.26,45.73 23.98,45.44 20.68,45.44 20.09,44.86 20.09,44.03 18.82,42.76 18.82,34.27 18.75,34.19 18.75,29.76 17.94,28.96 15.56,28.96 14.6,28 14.6,24.4 14.61,24.4 14.61,13.97 13.59,12.95 v1(13.59,4.19)
  L5_SIG w0.127: v1(45.13,1.94) 44.26,1.07 16.71,1.07 v1(13.59,4.19)
  BOTTOM w0.14: J2.93 v1(45.13,1.94)
PB_09/LP0_D2/SPI2_SEL7B/TM0_TMR7/TRACE0_D02: length 60.7
  TOP w0.203: U1.V6 v1(29.02,46.94)
  L4_SIG w0.127: v1(44.5,4.23) 44.16,3.89 43.93,3.89 41.55,1.51 40.27,1.51 39.5,2.29 39.5,4.45 37.74,6.2 37.74,13.53 38.3,14.09 38.3,17.15 36.5,18.96 36.5,40.21 34.04,42.67 33.66,42.67 33.15,43.18 33.15,47.12 32.91,47.35 29.43,47.35 v1(29.02,46.94)
  BOTTOM w0.14: J2.91 v1(44.5,4.23)
PB_10/LP0_D3/SPI1_SEL2B/PWM0_CH/TRACE0_D03: length 69.9
  TOP w0.14: v1(22.27,7.83) 22.27,7.12 22.7,6.7 42.28,6.7 42.79,6.2 42.79,3.01 v1(43.86,1.94)
  TOP w0.203: U1.Y3 v1(26.62,45.34)
  L4_SIG w0.127: v1(22.27,7.83) 22.27,12.14 21.72,12.7 21.72,29.25 22.81,30.34 22.81,40.08 23.24,40.51 23.24,43.05 24.89,44.7 26.47,44.7 26.62,44.86 v1(26.62,45.34)
  BOTTOM w0.14: J2.89 v1(43.86,1.94) ; J2.22 v1(22.27,7.83)
PB_11/LP0_D4/SPI0_RDY/PWM0_CL/UART2_RXB/TM0_ACI2: length 68.6
  TOP w0.14: v1(23.54,7.83) 24.13,7.24 28.03,7.24 v1(28.62,7.83) 29.42,7.03 43.13,7.03 43.69,6.48 43.69,4.69 v1(43.23,4.23)
  TOP w0.203: U1.Y4 v1(27.42,45.34)
  L4_SIG w0.127: v1(27.42,45.34) 27.42,44.86 26.76,44.2 25.65,44.2 25.02,43.56 25.02,42.44 24.65,42.07 24.65,40.59 23.8,39.74 23.8,30.87 22.05,29.11 22.05,13.05 23.54,11.55 v1(23.54,7.83)
  BOTTOM w0.14: J2.42 v1(28.62,7.83) ; J2.26 v1(23.54,7.83) ; J2.87 v1(43.23,4.23)
PB_12/LP0_D5/SPI2_SEL3B/PWM0_DH/UART2_TXB: length 67
  TOP w0.14: v1(27.99,5.54) 28.76,6.31 42.2,6.31 42.42,6.1 42.42,2.61 42.59,2.43 v1(42.59,1.94)
  TOP w0.203: U1.V7 v1(29.82,46.94)
  L4_SIG w0.127: v1(31.37,40.89) 31.71,40.55 31.71,36.54 30.56,35.38 30.56,28.4 28.7,26.54 28.7,18.8 29.97,17.53 29.97,15.75 29.46,15.24 29.46,10.54 27.99,9.06 v1(27.99,5.54)
  L5_SIG w0.127: v1(29.82,46.94) 30.23,46.53 30.23,44.31 30.35,44.2 30.86,44.2 31.37,43.69 v1(31.37,40.89)
  BOTTOM w0.14: J2.85 v1(42.59,1.94) ; J2.40 v1(27.99,5.54)
PB_13/LP0_D6/SPI1_SEL3B/XSPI0_DQSB_RWDS/UART2_RTSB: length 72.3
  TOP w0.14: v1(41.96,4.23) 41.4,4.78 41.4,5.59 41.01,5.98 29.7,5.98 v1(29.26,5.54) ; v1(32.89,38.1) 32.5,37.71 U27.12 ; U28.12 32.5,32.38 v1(32.89,32.77)
  TOP w0.203: U1.W5 v1(28.22,46.14)
  L4_SIG w0.127: v1(29.26,5.54) 29.94,6.22 33.15,6.22 34.42,7.49 34.42,8.89 36.58,11.05 36.58,13.84 37.47,14.73 37.47,16.51 35.94,18.03 34.92,18.03 34.16,18.8 34.16,20.45 34.8,21.08 34.8,27.43 34.04,28.19 33.02,28.19 32.38,28.83 32.38,32.26 v1(32.89,32.77) 32.38,33.27 32.38,37.59 v1(32.89,38.1)
  L5_SIG w0.127: v1(28.22,46.14) 28.63,45.73 28.63,44.58 30.1,43.11 30.1,38.99 30.35,38.73 32.26,38.73 v1(32.89,38.1)
  BOTTOM w0.14: J2.44 v1(29.26,5.54) ; J2.83 v1(41.96,4.23)
PB_13/LP0_D6/SPI1_SEL3B/XSPI0_DQSB_RWDS/UART2_RTSB_Z: length 38.1
  TOP w0.14: U28.11 v1(32.89,31.88)
  L5_SIG w0.127: v1(32.89,31.88) 31.65,33.12 29.36,33.12 28.93,32.69 28.93,27.84 27.79,26.7 27.79,18.67 26.12,17.01 26.12,12.13 26.51,11.74 26.51,7.26 25.98,6.73 25.98,4.83 25.39,4.23 v1(24.18,4.23)
  BOTTOM w0.14: J2.27 v1(24.18,4.23)
PB_14/LP0_D7/SPI0_SEL3B/PWM0_DL/UART2_CTSB: length 79.4
  TOP w0.14: v1(41.32,1.94) 41.79,1.48 44.15,1.48 44.45,1.78 44.45,2.54 44.94,3.03 44.94,6.5 44.07,7.37 30.35,7.37 v1(29.89,7.83)
  TOP w0.203: U1.Y14 v1(36.22,45.34)
  L4_SIG w0.127: v1(41.32,1.94) 42.42,3.04 42.42,5.71 41.53,6.6 39.5,6.6 38.73,7.37 38.73,13.12 39.29,13.68 39.29,17.57 37.59,19.27 37.59,21.04 38.18,21.62 38.18,27.38 38.99,28.19 40.26,28.19 41.02,28.96 41.02,30.82 41.02,30.82 41.02,31.36 41.02,31.36 41.02,33.95 41.18,34.11 41.18,38.54 39.52,40.21 38.66,40.21 35.81,43.05 35.81,44.45 36.22,44.86 v1(36.22,45.34)
  BOTTOM w0.14: J2.81 v1(41.32,1.94) ; J2.46 v1(29.89,7.83)
PB_15/LP1_D0/SPI0_SEL4B/SMC0_ADDR4: length 48.4
  TOP w0.203: U1.W14 v1(36.22,46.14)
  L4_SIG w0.127: v1(45.77,5.54) 44.32,6.98 43.94,6.98 43.05,7.87 43.05,11.81 44.32,13.08 44.32,15.49 44.7,15.88 44.7,23.88 44.22,24.36 44.22,25.88 42.2,27.9 42.2,30.1 41.35,30.95 41.35,31.23 41.35,31.23 41.35,33.81 41.51,33.97 41.51,38.68 39.65,40.54 39.6,40.54 39.55,40.59 38.91,40.59 36.63,42.87 36.63,45.73 v1(36.22,46.14)
  BOTTOM w0.14: J2.96 v1(45.77,5.54)
PC_00/LP1_D1/TWI4_SCL/TRACE0_D04/SPI1_SEL4B: length 52.4
  TOP w0.203: U1.V13 v1(35.42,46.94)
  L4_SIG w0.127: v1(39.37,5.52) 38.07,6.81 38.07,13.39 38.63,13.95 38.63,17.29 36.91,19.02 36.91,21.29 37.45,21.83 37.45,27.44 36.91,27.99 36.91,40.69 34.67,42.93 34.67,44.58 35.03,44.94 35.03,46.55 v1(35.42,46.94)
  BOTTOM w0.14: J2.94 45.13,5.61 44.6,5.08 39.81,5.08 v1(39.37,5.52)
PC_01/LP1_D2/TWI4_SDA/TRACE0_D05/SPI2_SEL4B: length 45
  TOP w0.203: U1.W15 v1(37.02,46.14)
  L4_SIG w0.127: v1(37.02,46.14) 37.43,45.73 37.43,43.08 39.26,41.25 39.88,41.25 42.17,38.95 42.17,33.9 42.67,33.4 42.67,30.67 42.86,30.48 42.86,28.38 44.88,26.37 44.88,24.84 45.52,24.21 45.52,12.97 43.73,11.18 43.73,8.6 v1(44.5,7.83)
  BOTTOM w0.14: J2.92 v1(44.5,7.83)
PC_02/LP1_D3/TWI5_SCL/TRACE0_D06/SPI1_SEL6B: length 43.9
  TOP w0.203: U1.Y15 v1(37.02,45.34)
  L4_SIG w0.127: v1(37.02,45.34) 37.02,43.03 39.13,40.92 39.74,40.92 41.84,38.82 41.84,33.84 41.68,33.68 41.68,31.09 42.53,30.24 42.53,28.21 44.55,26.19 44.55,24.54 45.09,24 45.09,15.75 44.65,15.32 44.65,12.69 43.4,11.43 43.4,8.29 v1(43.86,7.83)
  BOTTOM w0.14: J2.90 v1(43.86,7.83)
PC_03/LP1_D4/TWI5_SDA/TRACE0_D07/SPI2_SEL6B: length 55.4
  TOP w0.203: U1.W16 v1(37.82,46.14)
  L4_SIG w0.127: v1(43.23,5.54) 43.97,4.8 46.67,4.8 47.19,5.33 47.19,6.53 46.23,7.49 46.23,24.7 45.73,25.2 45.73,26.4 46.69,27.36 46.69,29.26 46.1,29.84 44.58,29.84 44.15,30.28 44.15,35.7 43.82,36.03 43.82,38.35 43.56,38.61 43.56,41.02 42.52,42.06 39.6,42.06 39.01,42.65 39.01,46.3 38.76,46.55 38.23,46.55 v1(37.82,46.14)
  BOTTOM w0.14: J2.88 v1(43.23,5.54)
PC_04/LP1_D5/XSPI0_SEL2B/PWM0_SYNC/SMC0_ADDR5: length 22.2
  TOP w0.14: U28.8 v1(31.75,30.18) ; U27.8 v1(31.75,35.51)
  TOP w0.203: U1.Y17 v1(38.62,45.34)
  L4_SIG w0.127: v1(31.75,30.18) v1(31.75,35.51)
  L5_SIG w0.127: v1(31.75,35.51) 31.75,37.21 32.21,37.67 33.22,37.67 33.53,37.97 33.53,39.5 34.42,40.39 37.47,40.39 38.62,41.54 v1(38.62,45.34)
PC_04/LP1_D5/XSPI0_SEL2B/PWM0_SYNC/SMC0_ADDR5_Z: length 41.6
  TOP w0.14: v1(32.89,30.1) 32.89,30.35 32.37,30.88 U28.9
  L5_SIG w0.127: v1(42.59,7.83) 42.16,8.26 39.11,8.26 38.48,8.89 38.48,18.54 36.58,20.45 36.58,26.42 40.13,29.97 40.13,32.13 39.95,32.31 38.07,32.31 37.67,31.9 35.94,31.9 34.8,30.76 34.8,29.92 34.52,29.64 33.35,29.64 v1(32.89,30.1)
  BOTTOM w0.14: J2.86 v1(42.59,7.83)
PC_05/LP1_D6/XSPI0_SEL3B/TM0_TMR8/SMC0_ADDR6: length 52.4
  TOP w0.203: U1.V14 v1(36.22,46.94)
  L4_SIG w0.127: v1(41.96,5.54) 41.28,6.22 39.37,6.22 38.4,7.19 38.4,13.25 38.96,13.81 38.96,17.43 37.24,19.16 37.24,21.15 37.78,21.69 37.78,27.5 38.86,28.57 40.13,28.57 40.51,28.96 40.51,33.95 40.85,34.29 40.85,38.41 39.38,39.88 38.35,39.88 35.03,43.2 35.03,44.3 35.81,45.08 35.81,46.53 v1(36.22,46.94)
  BOTTOM w0.14: J2.84 v1(41.96,5.54)
PC_06/LP1_D7/SPI1_RDY/PWM0_TRIPB/SMC0_ADDR7: length 56
  TOP w0.203: U1.W17 v1(38.62,46.14)
  L4_SIG w0.127: v1(41.32,7.83) 43.05,6.1 43.31,6.1 44.32,5.08 46.55,5.08 46.86,5.39 46.86,6.35 45.9,7.32 45.9,24.4 45.34,24.96 45.34,26.48 46.36,27.5 46.36,29.08 45.97,29.46 44.45,29.46 43.82,30.1 43.82,35.56 43.46,35.92 43.46,38.13 42.49,39.1 42.49,40.82 41.68,41.63 39.52,41.63 38.23,42.93 38.23,45.75 v1(38.62,46.14)
  BOTTOM w0.14: J2.82 v1(41.32,7.83)
PC_07/LP1_CLK/TM0_TMR9/SYS_FAULT*: length 48.5
  TOP w0.14: v1(39.42,45.34) 39.42,42.97 R23.1
  TOP w0.203: U1.Y18 v1(39.42,45.34)
  L4_SIG w0.127: v1(47.04,7.83) 46.58,8.28 46.58,25.12 47.02,25.55 47.02,29.44 46.23,30.23 44.7,30.23 44.48,30.45 44.48,35.83 44.2,36.11 44.2,38.48 44.58,38.86 44.58,41.02 43.18,42.42 39.88,42.42 39.42,42.88 v1(39.42,45.34)
  BOTTOM w0.14: J2.100 v1(47.04,7.83)
PG1: length 34.9
  TOP w0.254: VR1.1 19.63,13.99 19.86,13.76 19.86,13.26 19.87,13.26 19.87,12.96 20.06,12.77 R100.1 21.27,12.26 v2(21.08,12.06) ; v2(47.12,14.1) 46.81,14.4 46.73,14.4 46.46,14.67 U17.2
  L8_SIG w0.305: v2(21.08,12.06) 28.7,12.06 29.91,13.27 32.39,13.27 34.99,10.67 42.8,10.67 43.94,11.81 46.36,11.81 47.12,12.57 v2(47.12,14.1)
PG2: length 12.9
  TOP w0.254: U17.11 44.84,13.72 44.58,13.46 v2(43.56,13.46)
  TOP w0.305: R104.1 43.18,13.08 v2(43.56,13.46)
  L8_SIG w0.305: v2(34.92,14.6) 42.43,14.6 v2(43.56,13.46)
  BOTTOM w0.254: R92.1 v2(34.92,14.6)
SOM_TWI1_EN*: length 77.8
  TOP w0.14: v2(41.53,27.87) U3.1 43.75,27.87 44.45,27.18 45.97,27.18 46.67,27.87 U19.1 ; v2(12.57,56.39) 12.95,56.77 13.32,56.77 15.36,58.81 U24.10
  L7_SIG w0.127: v2(12.57,56.39) 12.57,54.94 7.42,49.79 7.42,35.13 9.32,33.22 9.32,28.4 v2(10.54,27.18)
  L8_SIG w0.127: v2(10.54,27.18) 11.3,27.94 16.64,27.94 17.02,27.56 32,27.56 32.32,27.87 v2(41.53,27.87)
  BOTTOM w0.14: R21.1 R19.2 42.36,27.87 v2(41.53,27.87)
SOM_TWI2_EN*: length 83.7
  TOP w0.14: v2(51.44,25.15) 51.44,24.33 51.57,24.19 U21.1 ; U24.9 14.86,58.93 13.21,57.28 v2(12.57,57.28) ; U20.1 v2(47.49,24.88)
  L5_SIG w0.127: v2(47.49,24.88) 47.99,24.38 50.67,24.38 v2(51.44,25.15)
  L7_SIG w0.127: v2(47.49,24.88) 46.98,25.4 39.36,25.4 36.95,27.81 30.1,27.81 29.46,28.45 10.41,28.45 9.65,29.21 9.65,33.4 7.75,35.31 7.75,49.65 13.27,55.17 13.27,56.58 v2(12.57,57.28)
  BOTTOM w0.14: v2(51.44,25.15) 51.44,24.26 R33.2 R34.1
SOM_XSPI_EN*: length 87.9
  TOP w0.14: v1(26.54,30.99) 26.15,31.38 U23.10 ; U30.1 v1(35.95,34.41) ; v1(39.24,33.66) 39.24,33.4 38.72,32.88 U30.13 ; v1(32.89,33.66) 32.89,33.4 32.37,32.88 U28.13 ; U28.4 v1(27.81,31.88) ; U30.4 v1(34.16,31.88) ; v2(16.76,58.55) 16.36,58.95 U24.12 ; v1(32.89,30.99) 32.5,31.38 U28.10 ; U23.13 26.02,32.88 26.54,33.4 v1(26.54,33.66) ; U28.1 v1(29.6,34.41) ; U23.1 v1(23.25,34.41) ; v1(39.24,30.99) 38.85,31.38 U30.10 ; U23.4 v1(21.46,31.88)
  L4_SIG w0.127: v1(26.54,33.66) 26.97,33.22 26.97,31.42 v1(26.54,30.99) ; v1(32.89,30.99) 33.32,31.42 33.32,33.22 v1(32.89,33.66) ; v1(39.24,30.99) 39.67,31.42 39.67,33.22 v1(39.24,33.66)
  L7_SIG w0.127: v1(17.53,36.32) 16.89,36.96 16.89,37.34 15.29,38.94 15.29,41.67 16.31,42.68 16.31,44.71 16.76,45.17 v2(16.76,58.55)
  L8_SIG w0.127: v1(35.95,34.41) 36.7,33.66 v1(39.24,33.66) ; v1(29.6,34.41) 30.35,33.66 v1(32.89,33.66) ; v1(21.46,31.88) 25.65,31.88 v1(26.54,30.99) 26.92,30.99 v1(27.81,31.88) 32,31.88 v1(32.89,30.99) 33.27,30.99 v1(34.16,31.88) 38.35,31.88 v1(39.24,30.99) ; v1(17.53,36.32) 18.29,37.08 20.7,37.08 21.03,36.75 21.79,36.75 23.25,35.29 v1(23.25,34.41) 24,33.66 v1(26.54,33.66)
  BOTTOM w0.14: v1(21.46,31.88) 22.1,31.88 22.36,31.62 R38.1 R37.2
SPI1D2_D3_EN*: length 29.4
  TOP w0.14: U5.1 v2(13.2,43.05) 12.85,43.4 9.17,43.4 8.88,43.11 U10.1 ; v2(11.81,60.2) 12.34,60.73 U24.6
  L4_SIG w0.127: v2(13.2,43.05) 12.26,43.99 12.26,54.99 13.77,56.5 13.77,59.26 12.83,60.2 v2(11.81,60.2)
  BOTTOM w0.14: v2(13.2,43.05) R54.1 R53.2
SPI1IFLASH_CS_EN*: length 28.5
  TOP w0.14: U9.1 v2(17.52,42.98) ; U24.5 v2(11.82,61.23)
  L4_SIG w0.127: v2(11.82,61.23) 12.41,61.23 14.1,59.54 14.1,56.2 12.64,54.74 12.64,44.89 14.03,43.5 17.01,43.5 v2(17.52,42.98)
  BOTTOM w0.14: R55.2 17.21,42.67 v2(17.52,42.98) 18.15,42.98 18.29,42.84 R56.1
SPIFLASH_CS*: length 14.2
  TOP w0.14: U9.4 20.03,40.1 20.03,38.58 19.4,37.94 15.79,37.94 15.24,37.39 15.24,34.4 U4.C2 15.75,33.91 16.16,33.5 17.75,33.5 18.16,33.91 R46.2
SPIFLASH_SPI1D2: length 13.5
  TOP w0.14: U4.C4 13.32,34.32 11.46,34.32 11.17,34.03 R48.2 9.53,34.03 8.89,34.67 8.89,37.47 9.78,38.35 11.18,38.35 11.81,38.99 11.81,39.98 11.48,40.32 U10.4
SPIFLASH_SPI1D3: length 14.6
  TOP w0.14: U5.4 15.5,39.25 14.99,38.73 12.19,38.73 11.3,37.85 9.92,37.85 9.4,37.33 9.4,35.33 9.54,35.19 R47.2 11.3,35.19 11.44,35.32 13.32,35.32 U4.D4
SYS_BMODE0: length 40.5
  TOP w0.14: 8.26,79.02 v2(8.26,80.9)
  TOP w0.203: U1.B10 v1(32.22,60.54)
  L7_SIG w0.127: v1(32.22,60.54) 32.22,61.25 22.48,70.99 11.43,70.99 9.02,73.41 9.02,80.14 v2(8.26,80.9)
  BOTTOM w0.14: v2(8.26,80.9) 8.26,79.83 R24.1
SYS_BMODE1: length 36.5
  TOP w0.14: v2(3.17,68.96) S1.2
  TOP w0.203: U1.B9 v1(31.42,60.54)
  L7_SIG w0.127: v2(3.17,68.96) 3.94,69.72 9.53,69.72 9.91,69.34 22.48,69.34 29.43,62.39 29.43,61.18 29.66,60.95 31.01,60.95 v1(31.42,60.54)
  BOTTOM w0.14: R25.1 3.05,69.85 3.05,69.09 v2(3.17,68.96)
SYS_BMODE2: length 42.8
  TOP w0.14: 3.17,79.02 v2(3.17,80.9)
  TOP w0.203: U1.A8 v1(30.62,61.34)
  L7_SIG w0.127: v2(3.17,80.9) 4.44,79.63 6.98,79.63 8.51,78.11 8.51,73.03 10.92,70.61 22.35,70.61 30.62,62.34 v1(30.62,61.34)
  BOTTOM w0.14: R26.1 3.17,79.88 v2(3.17,80.9)
SYS_CLKIN0: length 20
  TOP w0.14: R123.2 18.55,45.47 19.81,46.74 19.81,50.42 20.38,50.99 24.27,50.99 v1(25.02,51.74) ; R27.2 v1(19.81,52.45)
  TOP w0.203: U1.N1 v1(25.02,51.74)
  BOTTOM w0.14: v1(25.02,51.74) 24.56,52.2 20.07,52.2 v1(19.81,52.45)
SYS_CLKOUT: length 38.3
  TOP w0.203: U1.M3 v1(26.62,51.74)
  L8_SIG w0.127: v1(26.62,51.74) 26.21,51.33 17.16,51.33 16.13,50.29 11.05,50.29 8.51,47.75 8.51,42.67 6.6,40.77 6.6,33.53 v1(5.46,32.38)
  BOTTOM w0.14: v1(5.46,32.38) 6.65,32.38 J3.38
SYS_FAULT*: length 79.2
  TOP w0.14: U1.A11 28.83,65.53 v1(22.99,65.53) 22.99,66.2 22.85,66.34 R60.2 R59.2
  L4_SIG w0.127: v2(11.18,55.63) 11.81,54.99 11.81,46.1 7.62,41.91 7.62,33.66 8.71,32.56 8.71,17.2 v1(9.4,16.51)
  L5_SIG w0.127: v1(22.99,65.53) 22.35,64.9 22.35,59.69 21.08,58.42 18.41,58.42 15.9,55.91 13.74,55.91 13.05,55.21 11.59,55.21 v2(11.18,55.63)
  BOTTOM w0.14: J3.88 9.27,16.64 v1(9.4,16.51)
SYS_HWRST*: length 167.4
  TOP w0.14: U1.A9 29.24,63.52 22.32,63.52 R57.1 22.32,63.47 21.71,62.87 20.45,62.87 19.94,63.37 19.3,63.37 18.92,63.75 18.92,65.41 v2(18.16,66.17) 17.66,65.67 R64.2 17.22,65.67 16.45,64.9 16,64.9 15.86,64.76 U24.20 ; U4.A4 14.04,31.6 14.04,30.93 13.59,30.48 12.57,30.48 v2(11.94,31.11) ; R73.2 R75.2 57.42,22.33 U14.2 v1(55.5,23.8) ; U25.A4 v1(46.72,37.59)
  L4_SIG w0.127: v1(55.5,23.8) 53.92,23.8 53.34,24.38 53.34,26.29 51.44,28.19 49.53,28.19 48.9,28.83 48.9,35.42 v1(46.72,37.59) ; v1(9.4,14.22) 9.91,14.73 9.91,29.08 v2(11.94,31.11) 12.83,32 15.62,32 18.16,34.54 18.16,47.12 16.38,48.9 16.38,56.64 17.4,57.66 17.4,59.44 16.45,60.39 16.45,65.47 17.14,66.17 v2(18.16,66.17)
  L8_SIG w0.127: v1(55.5,23.8) 55.5,21.1 54.68,20.28 46.27,20.28 45.59,20.95 45.59,24.76 41.91,28.45 32.26,28.45 31.75,27.94 17.4,27.94 15.62,29.72 13.34,29.72 v2(11.94,31.11)
  BOTTOM w0.14: J3.94 8,14.73 8.26,14.73 8.89,14.73 v1(9.4,14.22)
SYS_RESOUT*: length 15.2
  TOP w0.14: R61.2 v1(23.02,64.79)
  TOP w0.203: U1.C10 v1(32.22,59.74)
  L7_SIG w0.127: v1(32.22,59.74) 31.81,59.33 24.62,59.33 24.13,59.82 24.13,63.68 v1(23.02,64.79)
SYS_XTAL0: length 7.2
  TOP w0.14: 25.02,52.54 24.61,52.13 20.38,52.13 19.43,51.18 R18.1
  TOP w0.203: U1.L1 25.02,52.54
TARGET_RESET*: length 124.4
  TOP w0.14: v1(54.61,39.37) 55.82,39.37 56.13,39.68 U11.1 ; R85.2 v2(10.79,48.9)
  L4_SIG w0.127: v2(10.79,48.89) 10.03,48.13 10.03,45.47 6.92,42.35 6.92,27.5 v1(8.26,26.16)
  L7_SIG w0.127: v1(54.61,39.37) 53.98,38.73 53.98,37.72 53.09,36.83 53.09,30.99 56.39,27.69 56.39,13.59 v1(55.25,12.45)
  L8_SIG w0.127: v1(8.26,26.16) 7.82,25.73 7.82,20.62 8.97,19.48 8.97,11.99 12.05,8.9 38.24,8.9 39.12,9.78 48.39,9.78 51.56,12.95 54.74,12.95 v1(55.25,12.45)
  BOTTOM w0.14: J3.58 v1(8.25,26.16) ; R63.2 v1(54.61,39.37)
TWI1_SCL: length 4.5
  TOP w0.14: U24.23 14.36,64.76 14.1,65.02 13.39,65.02 v2(12.7,65.72) R30.2
  BOTTOM w0.14: R30.2 v2(12.7,65.72)
TWI1_SDA: length 3.8
  TOP w0.14: R29.2 v2(13.97,65.72) 14.86,64.82 U24.22
  BOTTOM w0.14: R29.2 v2(13.97,65.72)
TWI2_SCL: length 54
  L5_SIG w0.127: v2(53.73,21.22) 52.83,20.32 47.71,20.32 47.5,20.11 47.5,16.64 50.67,13.46 50.67,7.54 51.79,6.42 51.79,3.74 51.4,3.35 48.67,3.35 47.33,4.7 40.3,4.7 38.12,2.51 29.7,2.51 v1(27.99,4.23)
  BOTTOM w0.14: R15.2 R13.2 v2(53.73,21.22) ; J2.39 v1(27.99,4.23)
TWI2_SDA: length 48.7
  L5_SIG w0.127: v2(49.28,21.21) 48.75,20.68 47.6,20.68 47.12,20.2 47.12,16.54 50.34,13.33 50.34,7.4 51.46,6.28 51.46,3.88 51.27,3.68 48.81,3.68 47.41,5.08 40.22,5.08 37.98,2.84 30.01,2.84 v1(28.62,4.23)
  BOTTOM w0.14: R14.2 R12.2 v2(49.28,21.21) ; J2.41 v1(28.62,4.23)
UART0_EN*: length 35.9
  TOP w0.14: U7.13 19.3,78.39 19.56,78.13 19.56,76.69 19.3,76.44 U7.10 16.78,76.44 16.64,76.58 v2(16,76.58) ; U24.7 13.86,59.2 13.72,59.05 v2(12.57,59.05)
  L4_SIG w0.127: v2(16,76.58) 16,75.95 13.21,73.15 9.65,73.15 8.64,72.14 8.64,61.72 11.3,59.05 v2(12.57,59.05)
  BOTTOM w0.14: v2(16,76.58) R82.1 R81.2
UART0_FLOW_EN*: length 37.3
  TOP w0.14: U24.8 14.36,59.07 13.46,58.17 v2(12.57,58.17) ; U7.4 13.84,77.09 v2(14.73,77.98) 13.67,79.04 U7.1
  L4_SIG w0.127: v2(12.57,58.17) 11.18,58.17 8.26,61.09 8.26,72.39 9.39,73.52 12.69,73.52 14.73,75.56 v2(14.73,77.98)
  BOTTOM w0.14: v2(14.73,77.98) R84.1 R83.2
UART_3V3_IO: length 55.1
  TOP w0.254: U15.6 14.88,89.46 14.29,90.04 13.6,90.04 C188.1
  TOP w0.508: DS7.A v2(4.45,99.57) ; DS8.A v2(6.35,99.57) ; C188.1 11.7,90.62 C187.1 9.69,90.64 9.18,90.13 v2(9.18,86.11) v2(9.96,86.11) R124.1
  L4_SIG w0.508: v2(6.35,99.57) v2(4.45,99.57) 3.94,99.57 3.17,98.81 3.17,90.81 7.87,86.11 v2(9.18,86.11) v2(9.96,86.11) 12.74,83.33 12.74,80.43 v2(12.19,79.88) 10.54,79.88 9.18,78.52 9.18,74.89 9.91,74.17 12.07,74.17 v2(12.19,74.29)
  BOTTOM w0.305: R87.1 v2(12.19,74.29)
  BOTTOM w0.508: R86.1 v2(12.19,79.88)
UNNAMED_3_ADSP21835_I66_HADC0VREFN: length 5.2
  TOP w0.14: R58.2 v1(42.98,51.74)
  TOP w0.203: U1.L18 v1(39.42,52.54)
  L5_SIG w0.127: v1(39.42,52.54) 39.81,52.15 42.57,52.15 v1(42.98,51.74)
UNNAMED_3_ADSP21835_I66_HADC0VREFP: length 19.1
  TOP w0.203: U1.L20 v1(41.02,52.54)
  TOP w0.508: FL2.3 50.94,57.23 50.43,57.74 C178.1 C177.1 v1(46.1,57.74)
  L8_SIG w0.508: v1(41.02,52.54) 46.44,52.54 46.99,53.09 46.99,56.85 v1(46.1,57.74)
UNNAMED_3_DIOLED_I14_N: length 2.9
  TOP w0.14: R59.1 21.32,68.69 21.46,68.83 22.29,68.83 22.43,68.97 DS6.C
UNNAMED_4_741G125_I12_B: length 2.2
  TOP w0.14: U20.4 50.1,22.29 50.28,22.11 v2(50.28,21.21)
  BOTTOM w0.14: R12.1 v2(50.28,21.21)
UNNAMED_4_741G125_I14_B: length 2.3
  TOP w0.14: U21.4 54.63,22.29 54.73,22.19 v2(54.73,21.21)
  BOTTOM w0.14: R13.1 v2(54.73,21.21)
UNNAMED_5_CAP_I8_N2: length 1.2
  BOTTOM w0.305: R17.1 C47.2
UNNAMED_5_CAP_I13_N1: length 13.2
  TOP w0.203: U1.L19 v1(40.22,52.54)
  TOP w0.508: v1(45.97,53.3) C44.1 47.07,53.22 C45.1 50.57,53.22 50.94,52.84 FL1.3
  L8_SIG w0.508: v1(40.22,52.54) 40.22,52.79 40.73,53.3 v1(45.97,53.3)
UNNAMED_5_FLTR3P_I3_IN: length 3.5
  TOP w0.508: R16.2 58,53.21 57.64,52.84 FL1.1
UNNAMED_7_CAP_I7_N1: length 5.3
  TOP w0.14: Y1.1 12.96,50.83 C166.1 12.96,48.89 13.21,48.64 15.25,48.64 R20.2
UNNAMED_7_CAP_I12_N1: length 6.1
  TOP w0.14: R27.1 17.78,52.32 R22.2 16.89,53.85 16.38,54.36 C168.1 15.2,54.32 Y1.3
UNNAMED_7_RES_I10_N2: length 3.1
  TOP w0.14: R18.2 17.78,51.32 R22.1 16.88,51.31 R20.1
UNNAMED_7_RES_I25_N2: length 1.6
  BOTTOM w0.14: Y5.1 R140.2
UNNAMED_7_RES_I31_N2: length 1.3
  BOTTOM w0.14: Y4.1 16.48,34.59 R139.2
UNNAMED_7_RES_I35_N2: length 1.5
  BOTTOM w0.14: Y6.1 15.31,23.63 15.31,23.63 R143.2
UNNAMED_7_RES_I51_N2: length 1.4
  TOP w0.14: Y2.1 12.71,45.47 R113.2
UNNAMED_7_RES_I59_N1: length 1.3
  BOTTOM w0.14: Y4.3 12.41,35.77 R141.1
UNNAMED_7_RES_I60_N1: length 1.5
  BOTTOM w0.14: Y5.3 R142.1
UNNAMED_7_RES_I61_N1: length 1.7
  BOTTOM w0.14: Y6.3 12.11,25.93 R144.1
UNNAMED_7_RES_I62_N1: length 1.4
  TOP w0.14: R123.1 16.76,46.48 Y2.3
UNNAMED_8_ICS71KLXXX_I51_CK: length 3.9
  TOP w0.14: U25.B2 v1(45.15,35.34)
  BOTTOM w0.14: v1(45.15,35.34) 44.55,35.94 R110.2
UNNAMED_8_ICS71KLXXX_I51_CS1: length 3.8
  TOP w0.14: U25.C2 v1(45.15,34.34)
  BOTTOM w0.14: R68.2 44.69,34.8 v1(45.15,34.34)
UNNAMED_8_ICS71KLXXX_I51_CS2: length 5.9
  TOP w0.14: U25.A3 v1(45.72,37.59)
  BOTTOM w0.14: v1(45.72,37.59) 45.24,37.12 44.04,37.12 42.93,38.23 R69.2
UNNAMED_8_ICS71KLXXX_I51_DQ0: length 5.7
  TOP w0.14: U25.D3 v1(46.15,32.48)
  BOTTOM w0.14: R119.1 48.72,35.5 48.72,34.94 48.38,34.59 48.38,34.3 47.51,33.44 47.11,33.44 v1(46.15,32.48)
UNNAMED_8_ICS71KLXXX_I51_DQ1: length 8.5
  TOP w0.14: U25.D2 v1(45.15,32.48)
  BOTTOM w0.14: v1(45.15,32.48) 44.58,31.9 44.58,30.1 45.09,29.58 48.52,29.58 R118.1
UNNAMED_8_ICS71KLXXX_I51_DQ2: length 5.5
  TOP w0.14: U25.C4 v1(47.15,34.34)
  BOTTOM w0.14: v1(47.15,34.34) 48.03,35.22 48.03,36.6 48.51,37.08 48.51,37.58 R117.1
UNNAMED_8_ICS71KLXXX_I51_DQ3: length 4
  TOP w0.14: U25.D4 v1(47.15,32.48)
  BOTTOM w0.14: v1(47.15,32.48) 47.81,33.13 47.81,33.25 48.68,34.12 48.72,34.12 48.72,34.36 R116.1
UNNAMED_8_ICS71KLXXX_I51_DQ4: length 2.7
  TOP w0.14: U25.D5 v1(48.15,32.48)
  BOTTOM w0.14: R115.1 48.83,33.78 48.15,33.11 v1(48.15,32.48)
UNNAMED_8_ICS71KLXXX_I51_DQ5: length 4.3
  TOP w0.14: U25.E3 v1(46.15,31.48)
  BOTTOM w0.14: R114.1 49.28,32.59 48.7,32 46.68,32 v1(46.15,31.48)
UNNAMED_8_ICS71KLXXX_I51_DQ6: length 7.2
  TOP w0.14: U25.E2 v1(45.15,31.48)
  BOTTOM w0.14: v1(45.15,31.48) 45.15,30.08 45.26,29.97 48.34,29.97 48.72,30.36 48.72,30.93 R112.1
UNNAMED_8_ICS71KLXXX_I51_DQ7: length 8
  TOP w0.14: U25.E1 v1(43.29,31.48)
  BOTTOM w0.14: R111.1 49.25,29.24 44.67,29.24 43.29,30.63 v1(43.29,31.48)
UNNAMED_8_ICS71KLXXX_I51_RWDS: length 6.3
  TOP w0.14: U25.C3 v1(46.15,34.34)
  BOTTOM w0.14: R120.1 48.38,36.3 48.38,35.08 48.03,34.74 48.03,34.44 47.37,33.78 46.74,33.78 46.18,34.34 v1(46.15,34.34)
UNNAMED_9_CAP_I3_N1: length 9.6
  TOP w0.305: v2(13.72,89.41) 14.1,89.41 14.37,89.13 U15.7
  TOP w0.508: R65.1 10.8,89.03 11.18,89.41 v2(13.72,89.41)
  BOTTOM w0.508: v2(13.72,89.41) 13.45,89.15 C186.1 11.26,89.15 C185.1 11.18,90.87 E1.2
UNNAMED_9_CMOSPI3C3125_I11_B0: length 17.5
  TOP w0.14: U7.3 11.32,77.74 v2(11.05,77.47) ; U15.23 18.78,85.36 18.99,85.15 18.99,84.64 v2(19.56,84.07)
  L4_SIG w0.127: v2(19.56,84.07) 19.56,81.79 17.7,79.93 13.51,79.93 v2(11.05,77.47)
  BOTTOM w0.14: v2(11.05,77.47) 11.44,77.86 R86.2
UNNAMED_9_CMOSPI3C3125_I11_B1: length 19.3
  TOP w0.14: v2(11.05,76.07) 11.43,75.79 U7.6 ; v2(19.56,85.09) 18.79,85.86 U15.24
  L4_SIG w0.127: v2(11.05,76.07) 14.58,79.6 18.14,79.6 20.07,81.53 20.07,84.58 v2(19.56,85.09)
  BOTTOM w0.14: R87.2 11.3,76.32 v2(11.05,76.07)
UNNAMED_9_CMOSPI3C3125_I11_B2: length 21.5
  TOP w0.14: v2(19.56,86.11) 19.3,86.36 U15.25 ; U7.8 19.3,75.14 v2(20.19,74.8)
  L4_SIG w0.127: v2(20.19,74.8) 21.21,75.82 21.21,87.88 20.83,88.27 19.3,88.27 18.92,87.88 18.92,86.74 v2(19.56,86.11)
UNNAMED_9_CMOSPI3C3125_I11_B3: length 18.1
  TOP w0.14: U7.11 16.89,77.09 v2(16.89,77.09) ; v2(19.56,87.12) 19.3,86.86 U15.26
  L4_SIG w0.127: v2(16.89,77.09) 16.31,77.09 16.19,77.21 15.69,77.21 15.37,77.53 15.37,78.74 15.9,79.27 18.44,79.27 20.57,81.41 20.57,86.11 v2(19.56,87.12)
UNNAMED_9_CN10PODDEVEN_I35_N5: length 4.4
  TOP w0.14: R85.1 8.01,49.91 P6.10
UNNAMED_9_DIOLED_I22_N: length 1.9
  TOP w0.14: R89.1 DS7.C
UNNAMED_9_DIOLED_I23_N: length 1.9
  TOP w0.14: R90.1 DS8.C
UNNAMED_9_ICCP2102NA_I49_GPIO: length 18.9
  TOP w0.14: R89.2 v2(4.45,93.34)
  TOP w0.203: v2(15.62,82.8) 15.88,83.06 U15.18
  L4_SIG w0.127: v2(15.62,82.8) 15.11,83.31 14.1,83.31 12.83,84.58 12.83,87 8.7,91.12 6.67,91.12 v2(4.45,93.34)
UNNAMED_9_ICCP2102NA_I49_GPIO_1: length 18
  TOP w0.14: R90.2 v2(6.35,93.34)
  TOP w0.203: U15.19 16.38,83.07 v2(16.64,82.8)
  L4_SIG w0.127: v2(16.64,82.8) 15.62,83.82 14.31,83.82 13.34,84.8 13.34,87.12 8.76,91.69 8,91.69 v2(6.35,93.34)
UNNAMED_9_ICCP2102NA_I49_RSTBN: length 2.2
  TOP w0.203: U15.9 12.94,87.36 12.7,87.12 12.7,87 R124.2
UNNAMED_9_ICCP2102NA_I49_VBUS: length 3
  TOP w0.254: R88.1 12.32,87.38 12.8,87.86 U15.8
  TOP w0.508: R88.1 R65.2
UNNAMED_10_7408V3_I4_Y: length 15.3
  TOP w0.14: v1(61.72,38.23) 60.96,37.78 59.57,37.78 U11.4 ; v1(61.72,30.86) 60.96,30.1 59.56,30.1 59.42,30.24 58.87,30.24 58.32,30.79 U13.1
  L4_SIG w0.127: v1(61.72,30.86) 62.48,31.62 62.48,37.46 v1(61.72,38.23)
UNNAMED_10_7408V3_I7_B: length 14
  TOP w0.14: U13.2 57.26,29.85 R70.2 55.11,29.85 54.23,30.73 54.23,32.51 54.86,33.15 54.86,34.93 55.66,35.72 S2.2 56.66,36 60.18,36 S2.3
UNNAMED_10_7408V3_I7_Y: length 8.8
  TOP w0.14: U13.4 60.31,28.9 60.71,28.5 60.71,24.26 60.25,23.8 U14.3 59.31,23.69 R71.2
UNNAMED_10_ADP5587_I68_C7: length 19.8
  TOP w0.14: U24.16 17.78,62.23 v2(18.16,61.85)
  TOP w0.305: v2(1.65,64.81) R72.2
  L5_SIG w0.127: v2(1.65,64.81) 3.24,63.22 16.03,63.22 17.02,62.23 17.78,62.23 v2(18.16,61.85)
UNNAMED_10_ADP5587_I68_C8: length 17.4
  TOP w0.14: U24.17 v2(18.15,62.73)
  TOP w0.305: R74.2 v2(3.56,64.81)
  L5_SIG w0.127: v2(18.15,62.73) 17.02,62.73 16.19,63.55 4.82,63.55 v2(3.56,64.81)
UNNAMED_10_ADP5587_I68_C9: length 15.7
  TOP w0.14: v2(18.16,63.63) 17.76,63.23 U24.18
  TOP w0.305: v2(5.46,64.81) R76.2
  L5_SIG w0.127: v2(18.16,63.63) 17.72,63.18 17.07,63.18 17.03,63.23 17.03,63.23 16.38,63.88 6.39,63.88 v2(5.46,64.81)
UNNAMED_10_DIOLED_I20_N: length 2.1
  TOP w0.14: R73.1 DS5.C
UNNAMED_10_DIOLED_I27_N: length 2.1
  TOP w0.14: R77.1 DS4.C
UNNAMED_10_DIOLED_I69_N: length 2.1
  TOP w0.14: R72.1 DS3.C
UNNAMED_10_DIOLED_I71_N: length 2.1
  TOP w0.14: R74.1 DS2.C
UNNAMED_10_DIOLED_I73_N: length 2.1
  TOP w0.14: R76.1 DS1.C
UNNAMED_12_CN100PV2_I10_N44: length 9.8
  TOP w0.14: v1(1.27,16.51) 1.73,16.05 1.73,13.51 4.45,10.79 R41.2
  BOTTOM w0.14: v1(1.27,16.51) 1.4,16.64 J3.87
UNNAMED_12_CN100PV2_I10_N45: length 8.5
  TOP w0.14: v1(1.27,15.75) 1.27,13.4 3.17,11.49 R42.2
  BOTTOM w0.14: v1(1.27,15.75) 1.52,16 J3.89
UNNAMED_12_CN100PV2_I10_N46: length 13.5
  TOP w0.14: R43.2 v2(6.98,10.79)
  BOTTOM w0.14: v2(6.98,10.79) 6.35,10.16 1.65,10.16 1.14,10.67 1.14,14.86 1.65,15.37 J3.91
UNNAMED_12_CN100PV2_I10_N47: length 6.2
  TOP w0.14: R44.2 v2(1.91,10.92)
  BOTTOM w0.14: J3.93 2.03,14.73 1.52,14.22 1.52,11.43 v2(1.91,10.92)
UNNAMED_12_CN100PV2_I10_N48: length 8.2
  TOP w0.14: v2(5.59,10.79) 5.59,10.15 R45.2
  BOTTOM w0.14: J3.95 2.16,14.1 1.91,13.84 1.91,12.06 3.17,10.79 v2(5.59,10.79)
UNNAMED_13_CAP_I3_N1: length 47.6
  TOP w0.203: 30.48,94.86 P1.SH5 30.48,96.35 ; 30.48,97.95 P1.SH6 30.48,99.45
  TOP w0.508: P1.SH3 27.06,99.31 ; P1.SH3 25.36,99.31 ; P1.SH3 27.06,96.99 ; P1.SH3 25.36,96.99 ; P1.SH4 35.6,99.31 ; P1.SH4 33.9,99.31 ; P1.SH4 33.9,96.99 ; P1.SH4 35.6,96.99 ; 25.36,94.58 P1.SH2 ; P1.SH2 27.06,94.58 ; P1.SH2 25.36,92.26 ; P1.SH1 35.6,94.58 ; P1.SH1 33.9,94.58 ; P1.SH1 35.6,92.26
  BOTTOM w0.508: 25.36,96.99 P1.SH3 ; P1.SH3 24.85,98.15 24.31,98.69 C184.1 R80.1 ; P1.SH3 25.36,99.31 ; P1.SH3 27.06,96.99 ; P1.SH3 27.06,99.31 ; P1.SH4 35.6,99.31 ; P1.SH4 35.6,96.99 ; P1.SH4 33.9,96.99 ; P1.SH4 33.9,99.31 ; 33.9,94.58 P1.SH1 ; P1.SH1 35.6,94.58 ; P1.SH1 35.6,92.26 ; 25.36,94.58 P1.SH2 ; P1.SH2 25.36,92.26 ; P1.SH2 27.06,94.58
UNNAMED_13_CN24PAB2GND6SHLD_I10_N5: length 7.2
  TOP w0.305: P1.A5 31.23,90.31 31.25,90.29 31.25,90.29 31.44,90.1 31.44,90.1 31.62,89.92 31.62,88.24 31.32,87.93 D17.3 v2(30.59,87.21)
  BOTTOM w0.14: R6.1 29.27,87.76 29.82,87.21 v2(30.59,87.21)
UNNAMED_13_CN24PAB2GND6SHLD_I11_N5: length 11.8
  TOP w0.305: D17.1 v2(29.59,89.23)
  L4_SIG w0.305: v2(29.59,89.23) 27.93,89.23 26.92,90.23 26.92,92.52 27.39,92.99 27.39,93.42 27.76,93.79 29.38,93.79 29.68,93.48 P1.B5
  BOTTOM w0.14: R66.1 29.26,88.9 v2(29.59,89.23)
UNNAMED_14_ADLT8636_I23_BST: length 1.9
  TOP w0.254: C207.1 18.78,19 VR1.7
UNNAMED_14_ADLT8636_I23_EN: length 2.6
  TOP w0.203: v1(15.94,14.99) 16.14,14.99 VR1.14
  BOTTOM w0.305: v1(15.94,14.99) 15.93,14.99 15.62,15.29 R96.2 R95.2
UNNAMED_14_ADLT8636_I23_FB1: length 5.2
  TOP w0.254: VR1.19 18.28,12.7 ; 18.28,12.7 18.54,12.7 18.53,12.7 18.78,12.95 VR1.20 ; 18.28,12.7 18.28,11.35 C210.2
  TOP w0.305: C210.2 R105.2 R106.1
UNNAMED_14_ADLT8636_I23_RT: length 2.5
  TOP w0.254: VR1.17 17.28,13.09 16.13,11.94 R98.1
UNNAMED_14_ADLT8636_I23_SYNC: length 2.6
  TOP w0.254: VR1.15 16.2,14.49 15.55,13.84
  TOP w0.305: R93.1 R94.1 15.55,13.84
